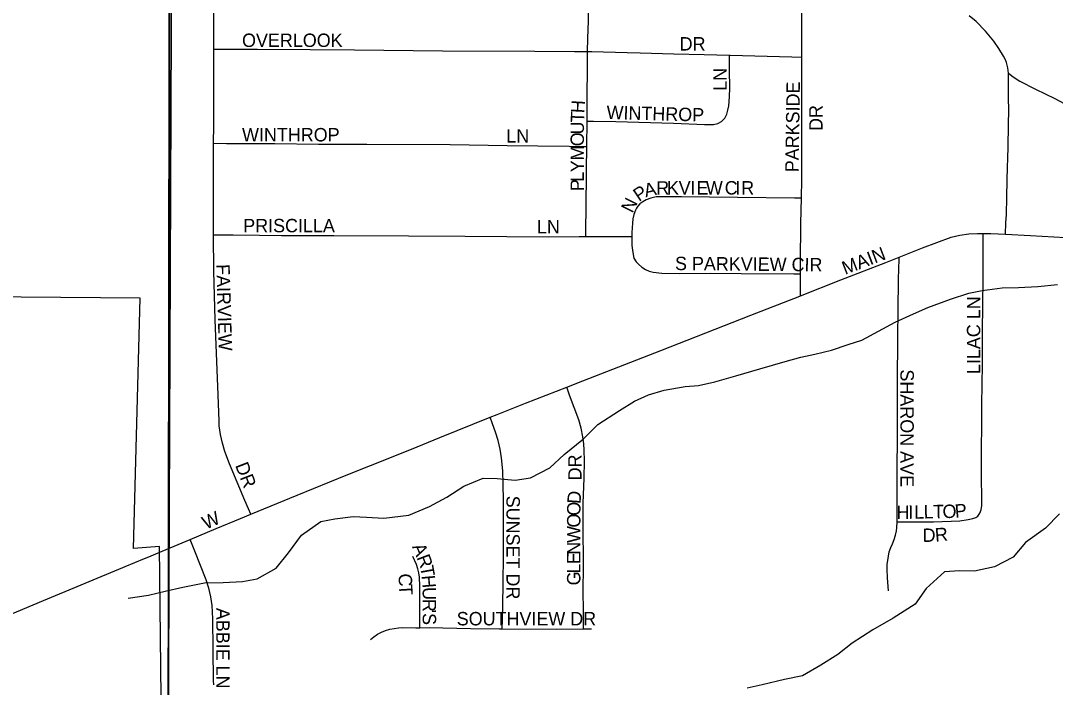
# Model space of a CAD drawing. Extents: x 1874609 to 2204689, y 815661 to 1281160.
# Drawn here: x 2012353 to 2016212, y 1043764 to 1046249 of the extents above; entities that cross this region are included whole.
import ezdxf

# ---------------------------------------------------------------- set-up
doc = ezdxf.new("R2010")
doc.units = 0
for name, color, linetype in [('GM_X_City_Street', 7, 'Continuous'), ('GM_X_City_Street_Text', 7, 'Continuous'), ('GM_X_Corporation', 7, 'Continuous'), ('GM_X_County_Road', 7, 'Continuous'), ('GM_X_Minor_River', 7, 'Continuous'), ('GM_X_Section', 7, 'Continuous'), ('GM_X_Township', 7, 'Continuous')]:
    doc.layers.add(name, color=color, linetype=linetype)

msp = doc.modelspace()

# ---------------------------------------------------------------- linework, layer by layer
at = {"layer": 'GM_X_City_Street'}
for points in [[(2014467, 1046133.5), (2014468, 1046182.8), (2014470.4, 1046248.3), (2014470.7, 1046330.4), (2014471.3, 1046363.2), (2014470.3, 1046444.9), (2014469.9, 1046481.1)], [(2015267, 1046113.2), (2015267.1, 1046181), (2015266.6, 1046262.6), (2015267.1, 1046376.9), (2015267.9, 1046474.8), (2015268, 1046477)], [(2013073.1, 1046143.1), (2013073.4, 1046335.8), (2013076.1, 1046352), (2013080.2, 1046367.8), (2013086.5, 1046383), (2013102.3, 1046411.9)], [(2016037.5, 1046053.3), (2016035.2, 1046072.9), (2016030.4, 1046092.7), (2016026.6, 1046102.2), (2016018.9, 1046117), (2016001.7, 1046145.4), (2015982.5, 1046172.2), (2015951, 1046210.1), (2015916.2, 1046245.4), (2015891, 1046266.9)], [(2013072.5, 1045791.7), (2013073.2, 1045858.2), (2013073.5, 1046022.9), (2013073.1, 1046138.2), (2013073.1, 1046143.1)], [(2013073.1, 1046143.1), (2013101.5, 1046143), (2013154, 1046142.7), (2013236.1, 1046142.5), (2013433.1, 1046141.1), (2013597.4, 1046140.1), (2013925.7, 1046136.9), (2014270.4, 1046135.6), (2014418.1, 1046134), (2014467, 1046133.5)], [(2014465.2, 1045874.2), (2014465.6, 1045920.7), (2014466.6, 1046117.4), (2014467, 1046133.5)], [(2014467, 1046133.5), (2014483.7, 1046133.4), (2014614.8, 1046129.9), (2014663.6, 1046128.3), (2014789.5, 1046125.4), (2014901.9, 1046123), (2014996.7, 1046120.6)], [(2014465.2, 1045874.2), (2014489.9, 1045873.9), (2014572.6, 1045872.6), (2014787.8, 1045867.3), (2014903.5, 1045862), (2014936.6, 1045861.6), (2014952.6, 1045865.7), (2014967.4, 1045873.2), (2014978.8, 1045884.9), (2014986.3, 1045899.7), (2014991, 1045915.6), (2014994, 1045931.9), (2014996.7, 1045964.9), (2014997.4, 1045998), (2014996.5, 1046064.2), (2014996.7, 1046111.4), (2014996.7, 1046120.6)], [(2014996.7, 1046120.6), (2014999.7, 1046120.6), (2015229, 1046114.2), (2015267, 1046113.2)], [(2015264.7, 1045587.1), (2015266, 1045657.1), (2015266, 1045754.4), (2015266, 1045829.5), (2015266.3, 1045859.9), (2015266.7, 1045891.4), (2015267.1, 1046002.4), (2015266.9, 1046034.9), (2015267, 1046113.2)], [(2016025.8, 1045452.7), (2016028, 1045494.9), (2016029.7, 1045526.8), (2016031.4, 1045591), (2016032.4, 1045654.7), (2016033.5, 1045702.2), (2016035, 1045734.6), (2016035.8, 1045778.4), (2016037.3, 1045859.7), (2016038.1, 1045917.3), (2016037.9, 1045958.2), (2016037.6, 1046024.5), (2016037.5, 1046053.3)], [(2016037.5, 1046053.3), (2016055.2, 1046039.1), (2016080, 1046022.9), (2016137.7, 1045993.9), (2016210.1, 1045958.1), (2016295.8, 1045912.2), (2016351.9, 1045879.7), (2016392.3, 1045852.7), (2016437.2, 1045821.3), (2016480.9, 1045788.3), (2016520.8, 1045758.4), (2016556.9, 1045728.4), (2016584.4, 1045704.6), (2016607.8, 1045684.2)], [(2014464.3, 1045779.7), (2014465.2, 1045874.2)], [(2013072.3, 1045450.8), (2013072.2, 1045479.7), (2013072.5, 1045627.9), (2013071.8, 1045726.6), (2013072.5, 1045791.7)], [(2013072.5, 1045791.7), (2013120.2, 1045791.4), (2013132.5, 1045791.4), (2013300.2, 1045790.3), (2013463.8, 1045788.4), (2013643.7, 1045788.2), (2013954.5, 1045786.6), (2014167.1, 1045783.8), (2014281.5, 1045782.7), (2014399.1, 1045780.8), (2014448.3, 1045780), (2014464.3, 1045779.7)], [(2014460.4, 1045444), (2014461.1, 1045477.4), (2014462.6, 1045543.2), (2014463.6, 1045690.9), (2014464.3, 1045779.7)], [(2015264.7, 1045587.1), (2015239.2, 1045587.1), (2015026.4, 1045589.3), (2014817.5, 1045592.6), (2014748.2, 1045592.6), (2014723.5, 1045591.5), (2014702.7, 1045587.1), (2014685.4, 1045580.7), (2014672.9, 1045574.1), (2014662.3, 1045566), (2014655.3, 1045557.8)], [(2015261.7, 1045304.7), (2015261.6, 1045346.7), (2015262.9, 1045493.6), (2015264.7, 1045587.1)], [(2014655.3, 1045557.8), (2014650.1, 1045550.2), (2014645.9, 1045542), (2014640.1, 1045526.5), (2014636.6, 1045510.4), (2014634.4, 1045494), (2014632.1, 1045458.6), (2014632.3, 1045443.7)], [(2013072.3, 1045450.8), (2013101.4, 1045450.8), (2013145.6, 1045450.9), (2013243.6, 1045448.7), (2013325.3, 1045448.5), (2013521.3, 1045448.4), (2013798.9, 1045447.1), (2014011.2, 1045445.2), (2014321.4, 1045443.2), (2014435.8, 1045444.1), (2014460.4, 1045444)], [(2013210.8, 1044409.2), (2013202.2, 1044429.6), (2013189.4, 1044460), (2013132.2, 1044596.7), (2013114.7, 1044642.9), (2013105.3, 1044674.4), (2013098.3, 1044706.5), (2013093.6, 1044739.1), (2013092.5, 1044755.5), (2013089.7, 1044854.1), (2013078.4, 1045133.9), (2013072.7, 1045315), (2013072.3, 1045450.8)], [(2014460.4, 1045444), (2014599, 1045443.8), (2014632.3, 1045443.7)], [(2014632.3, 1045443.7), (2014632.9, 1045411), (2014635.8, 1045384.9), (2014640.2, 1045363.9)], [(2015630, 1045366.8), (2015716.6, 1045401.4), (2015823.8, 1045441.3), (2015839.7, 1045446), (2015856, 1045449.7), (2015888.9, 1045454), (2015922, 1045455.6), (2015943.5, 1045455.5)], [(2015922.7, 1044402.2), (2015930, 1044413.5), (2015935.1, 1044425.4), (2015937.9, 1044441.8), (2015937.9, 1044475.7), (2015937, 1044539.2), (2015936.5, 1044654.8), (2015937.8, 1044736.8), (2015938.1, 1044818.4), (2015940.4, 1044966.6), (2015939.9, 1045032.2), (2015940.7, 1045114.4), (2015941.5, 1045164), (2015942.1, 1045213.2), (2015942.4, 1045262.6), (2015943.5, 1045344.7), (2015943.5, 1045377.8), (2015943.5, 1045410.8), (2015943.5, 1045455.5)], [(2015943.5, 1045455.5), (2015971.4, 1045455.4), (2016025.8, 1045452.7)], [(2016025.8, 1045452.7), (2016118.9, 1045448.1), (2016380.8, 1045433.7), (2016578.2, 1045426.2)], [(2014640.2, 1045363.9), (2014648.8, 1045350.3), (2014657.5, 1045341.1), (2014670, 1045329.8), (2014683, 1045321.4), (2014697.3, 1045315.5), (2014712.5, 1045311.7), (2014744.3, 1045308.1), (2014809.5, 1045306.1), (2014924.8, 1045307), (2015039.7, 1045306.4), (2015236.2, 1045304.9), (2015261.7, 1045304.7)], [(2015261.7, 1045223.4), (2015411.5, 1045282.7), (2015579.8, 1045346.8), (2015630, 1045366.8)], [(2015622.4, 1044381), (2015621.8, 1044430.2), (2015621.8, 1044476.4), (2015622.6, 1044606.4), (2015622.9, 1044665.3), (2015623.4, 1044735.3), (2015622.9, 1044790.8), (2015623.2, 1044848.4), (2015623.6, 1044961.7), (2015624.1, 1045005.5), (2015625.2, 1045073.3), (2015626.3, 1045167.1), (2015627.5, 1045285.8), (2015629.7, 1045359.3), (2015630, 1045366.8)], [(2015261.7, 1045223.4), (2015261.7, 1045265.9), (2015261.7, 1045304.7)], [(2014389.6, 1044882.9), (2014450.1, 1044906.5), (2014740.4, 1045019.5), (2014908.5, 1045084.9), (2015076.1, 1045151.2), (2015259.4, 1045222.4), (2015261.7, 1045223.4)], [(2014103.5, 1044770.4), (2014129.5, 1044780.9), (2014236.2, 1044823), (2014389.6, 1044882.9)], [(2014451.7, 1043981.4), (2014451.6, 1044015.2), (2014451.5, 1044042.5), (2014451.4, 1044129.5), (2014451.7, 1044206.5), (2014451.5, 1044269.4), (2014451.3, 1044318.8), (2014451.1, 1044450.3), (2014454, 1044542.9), (2014455.3, 1044608.6), (2014454.1, 1044647.2), (2014452.8, 1044672), (2014449.5, 1044697.1), (2014443.3, 1044729.6), (2014434.6, 1044761.2), (2014400.5, 1044853.2), (2014389.6, 1044882.9)], [(2013210.8, 1044409.2), (2013384.6, 1044480.4), (2013567, 1044554.2), (2013658.2, 1044590.8), (2013810.4, 1044651.8), (2013916.7, 1044695), (2014103.5, 1044770.4)], [(2014149.3, 1043981.6), (2014149.9, 1044014.6), (2014152.3, 1044141.8), (2014153.6, 1044263.5), (2014153.6, 1044459.7), (2014152.6, 1044521.2), (2014151.4, 1044570.4), (2014146.4, 1044619.3), (2014141, 1044651.7), (2014133.7, 1044683.6), (2014124, 1044715), (2014112.6, 1044745.8), (2014103.5, 1044770.4)], [(2012984.7, 1044314.9), (2013081.4, 1044355.6), (2013172.2, 1044393.4), (2013210.8, 1044409.2)], [(2015622.4, 1044381), (2015639, 1044380.8), (2015676.8, 1044380.2), (2015758.2, 1044381.2), (2015855.5, 1044385), (2015887.5, 1044389.2), (2015904, 1044392.6), (2015915.3, 1044396.6), (2015922.7, 1044402.2)], [(2015589.5, 1044123.4), (2015588.5, 1044139.5), (2015586, 1044172), (2015585, 1044204.8), (2015585.4, 1044221.1), (2015589.5, 1044253.3), (2015592.4, 1044269.3), (2015597.9, 1044284.6), (2015605.1, 1044299.2), (2015610.5, 1044314.5), (2015615.8, 1044330.5), (2015619.2, 1044346.9), (2015620.9, 1044359.9), (2015622.4, 1044381)], [(2012847.6, 1044257.4), (2012880.6, 1044271.1), (2012984.7, 1044314.9)], [(2013072.6, 1043772.6), (2013072.2, 1043789.1), (2013070.7, 1043904.3), (2013069.6, 1044019.6), (2013067.2, 1044068.9), (2013062.6, 1044101.5), (2013055, 1044133.5), (2013044.9, 1044164.8), (2013001.9, 1044271.8), (2012984.7, 1044314.9)], [(2013841.8, 1043986.1), (2013841.7, 1044026.9), (2013841.4, 1044141.5), (2013839.9, 1044174.2), (2013837.7, 1044190.3), (2013834.2, 1044206.1), (2013828.7, 1044221.6), (2013815, 1044251.3)], [(2013658.1, 1043942), (2013670.6, 1043952.5), (2013684.1, 1043961.8), (2013698.5, 1043969.6), (2013713.7, 1043975.7), (2013729.3, 1043980.4), (2013745.3, 1043983.5), (2013761.6, 1043985.3), (2013778, 1043986.2), (2013827.1, 1043986.1), (2013841.8, 1043986.1)], [(2013841.8, 1043986.1), (2013876.1, 1043986.3), (2014030.6, 1043982.9), (2014138.3, 1043981.7), (2014149.3, 1043981.6)], [(2014149.3, 1043981.6), (2014351.2, 1043980.3), (2014451.7, 1043981.4)], [(2014451.7, 1043981.4), (2014482, 1043981.8)]]:
    msp.add_lwpolyline(points, dxfattribs=at)
at = {"layer": 'GM_X_Corporation'}
msp.add_lwpolyline([(2010048.7, 1041405.7), (2010287.2, 1041403.4), (2010287.3, 1041646.5), (2010579.3, 1041646.5), (2010579.4, 1043188.1), (2011124.6, 1043188), (2011247.5, 1042490.5), (2012113.3, 1042894.2), (2012352.9, 1041534.6), (2012140.1, 1041385.6), (2013525.3, 1041372.3), (2013561.3, 1042582.1), (2012889.8, 1042600.8), (2012870.5, 1044289.2), (2012774, 1044281.2), (2012798.1, 1045214.1), (2010579, 1045233.5), (2010579.1, 1046516.9), (2010425.9, 1046511), (2010421.8, 1047312.9), (2010245.1, 1047314.3)], dxfattribs=at)
at = {"layer": 'GM_X_County_Road'}
msp.add_lwpolyline([(2010258.4, 1043876.4), (2010450.6, 1043874.2), (2010598.2, 1043872.7), (2011139.3, 1043861.3), (2011336, 1043855.8), (2011680.2, 1043849.1), (2011745.5, 1043849.5), (2011794.4, 1043852.4), (2011842.8, 1043858.6), (2011890.6, 1043868.5), (2011937.5, 1043881.9), (2011998.8, 1043904.3), (2012119.8, 1043954.3), (2012437.4, 1044088), (2012734.3, 1044211), (2012742.7, 1044214.4), (2012814.2, 1044243.4), (2012830.4, 1044250.1), (2012847.6, 1044257.4)], dxfattribs=at)
at = {"layer": 'GM_X_Minor_River'}
for points in [[(2012753.2, 1044096.1), (2012829.4, 1044107.9), (2012891.6, 1044121.7), (2012957.9, 1044137.5), (2013038.1, 1044153.3), (2013108.3, 1044155), (2013180.6, 1044158.8), (2013234.8, 1044168.7), (2013305.1, 1044208.5), (2013351.4, 1044264.6), (2013399.7, 1044330.6), (2013472, 1044382.5), (2013524.2, 1044392.4), (2013592.4, 1044400.2), (2013642.6, 1044398), (2013706.8, 1044393.8), (2013801.1, 1044405.5), (2013877.4, 1044437.3), (2013941.7, 1044473.2), (2014006, 1044513.1), (2014078.3, 1044542.9), (2014130.4, 1044542.8), (2014196.6, 1044536.5), (2014254.8, 1044544.3), (2014327.1, 1044582.2), (2014379.4, 1044632.2), (2014451.8, 1044690.1), (2014506.1, 1044744.1), (2014586.4, 1044796), (2014642.7, 1044829.9), (2014694.9, 1044853.8), (2014753.1, 1044871.7), (2014831.4, 1044885.4), (2014881.6, 1044889.3), (2014941.8, 1044903.1), (2015020.1, 1044924.9), (2015110.4, 1044950.7), (2015204.8, 1044978.5), (2015263, 1044994.3), (2015315.2, 1045006.2), (2015377.4, 1045020), (2015439.6, 1045041.8), (2015489.8, 1045057.7), (2015614.4, 1045125.5), (2015682.7, 1045155.4), (2015736.9, 1045179.3), (2015821.2, 1045211.1), (2015889.5, 1045232.9), (2015939.6, 1045242.8), (2016013.9, 1045252.5), (2016074.1, 1045254.3), (2016146.3, 1045258.1), (2016220.5, 1045265.9)], [(2016228.1, 1044411), (2016175.8, 1044357), (2016101.4, 1044303.1), (2016055.2, 1044249.1), (2015984.8, 1044213.2), (2015910.6, 1044197.4), (2015854.4, 1044197.6), (2015798.2, 1044193.8), (2015729.9, 1044131.9), (2015689.6, 1044073.8), (2015607.2, 1044021.9), (2015530.9, 1043978), (2015454.5, 1043928.1), (2015400.2, 1043886.2), (2015337.9, 1043846.3), (2015269.6, 1043806.4), (2015201.4, 1043792.6), (2015119.1, 1043772.8), (2015062.9, 1043761)]]:
    msp.add_lwpolyline(points, dxfattribs=at)
at = {"layer": 'GM_X_Section'}
for points in [[(2012915.3, 1046513.3), (2012892.7, 1041156.5), (2007599.8, 1041247.3), (2007626.4, 1046598.1)], [(2019020.7, 1046448.2), (2018988, 1041097.3), (2012892.7, 1041156.5), (2012915.3, 1046513.3)]]:
    msp.add_lwpolyline(points, close=True, dxfattribs=at)
at = {"layer": 'GM_X_Township'}
for points in [[(2012924.9, 1056002.2), (2012935.3, 1053679.3), (2012914.5, 1051827.7), (2012910.2, 1048822.6), (2012903.7, 1044302.1), (2012899.1, 1041173.4), (2012896.1, 1039044.8), (2012861.2, 1035880.2), (2012864.4, 1032937.1), (2012859.2, 1032479.4), (2012845.9, 1030538.4), (2012837.6, 1027645.9), (2012830.6, 1025241.9), (2010175.8, 1025275.6)], [(2037504.4, 1025002.2), (2030477.9, 1025070.5), (2023338.3, 1025139.8), (2019554.9, 1025176.6), (2018880.2, 1025183.1), (2014559, 1025225.1), (2013359, 1025236.7), (2012830.6, 1025241.9), (2012837.6, 1027645.9), (2012845.9, 1030538.4), (2012859.2, 1032479.4), (2012864.4, 1032937.1), (2012861.2, 1035880.2), (2012896.1, 1039044.8), (2012899.1, 1041173.4), (2012903.7, 1044302.1), (2012910.2, 1048822.6), (2012914.5, 1051827.7), (2012935.3, 1053679.3), (2012924.9, 1056002.2)]]:
    msp.add_lwpolyline(points, dxfattribs=at)

# ---------------------------------------------------------------- texts
at = {"layer": 'GM_X_City_Street_Text'}
for s, rotation, p in [('OVERLOOK', 0, (2013178.4, 1046150.7)), ('DR', 0, (2014810.8, 1046137.5)), ('LN', 90, (2014986.2, 1045987.3)), ('PARKSIDE', 89.1565, (2015254.5, 1045683.5)), ('H', 87.0263, (2014455.3, 1045903)), ('WINTHROP', 358.453, (2014537.6, 1045882.3)), ('DR', 90, (2015344, 1045837.7)), ('T', 87.8415, (2014454, 1045868)), ('U', 89.6721, (2014453.8, 1045824.5)), ('WINTHROP', 0, (2013178.4, 1045798.7)), ('LN', 0, (2014164, 1045794.3)), ('O', 89.9928, (2014453.8, 1045780.5)), ('M', 89.9818, (2014453.8, 1045727.7)), ('Y', 89.9781, (2014453.8, 1045683.7)), ('L', 89.9956, (2014453.8, 1045648.5)), ('P', 89.9727, (2014453.7, 1045613.3)), ('P', 33.8795, (2014659, 1045572.4)), ('A', 13.5221, (2014684, 1045590.1)), ('R', 0.9472, (2014723.9, 1045600)), ('K', 0.0437, (2014763.3, 1045600.7)), ('V', 0, (2014807.2, 1045600.7)), ('I', 0, (2014851.2, 1045600.7)), ('E', 0, (2014873.2, 1045600.7)), ('W', 0, (2014908.4, 1045600.7)), ('C', 0, (2014978.8, 1045600.7)), ('I', 0, (2015018.4, 1045600.7)), ('R', 0, (2015040.4, 1045600.7)), ('N', 63.7087, (2014634.7, 1045528.7)), ('PRISCILLA', 0, (2013182.8, 1045459.9)), ('LN', 0, (2014278.4, 1045455.5)), ('MAIN', 20.925, (2015427.8, 1045300.9)), ('S PARKVIEW CIR', 359.4792, (2014793.3, 1045319.1)), ('FAIRVIEW', 271.706, (2013082.2, 1045340.6)), ('LILAC LN', 90, (2015932.1, 1044931.3)), ('SHARON AVE', 270, (2015634.2, 1044948.9)), ('DR', 90, (2014445, 1044535.3)), ('DR', 291.2529, (2013151.9, 1044591.5)), ('SUNSET DR', 270, (2014164.6, 1044478.1)), ('D', 86.0841, (2014441, 1044446.4)), ('O', 89.4754, (2014440.7, 1044403.2)), ('H', 1.2458, (2015620.2, 1044390.7)), ('I', 1.2245, (2015664.2, 1044391.7)), ('L', 1.2378, (2015686.2, 1044392.1)), ('L', 1.2495, (2015721.4, 1044392.9)), ('T', 1.2293, (2015756.6, 1044393.7)), ('O', 1.2438, (2015791.8, 1044394.4)), ('P', 4.694, (2015839.1, 1044395.5)), ('W', 24.5873, (2013043.9, 1044350.9)), ('O', 89.9781, (2014440.6, 1044359.3)), ('W', 89.9798, (2014440.6, 1044302.1)), ('D', 1.071, (2015717.4, 1044305.6)), ('R', 4.9331, (2015765, 1044306.6)), ('A', 292.8771, (2013811.8, 1044288.3)), ('N', 89.9703, (2014440.6, 1044258.1)), ('R', 290.6243, (2013828.7, 1044248.2)), ('E', 89.9707, (2014440.6, 1044222.9)), ('T', 280.2438, (2013842, 1044213.5)), ('L', 89.9727, (2014440.6, 1044187.7)), ('C', 272.1858, (2013761.8, 1044187.2)), ('H', 274.9234, (2013848.1, 1044180.1)), ('G', 89.9781, (2014440.6, 1044143.7)), ('T', 273.292, (2013763.3, 1044146.6)), ('U', 270.4591, (2013851.8, 1044137.2)), ('R', 270, (2013852.2, 1044093.4)), ('ABBIE LN', 270, (2013082, 1044060.1)), ("'", 269.9895, (2013852.2, 1044053.8)), ('SOUTHVIEW DR', 0, (2013979.2, 1043994.7)), ('S', 269.9956, (2013852.2, 1044040.6))]:
    msp.add_text(s, height=50, rotation=rotation, dxfattribs=at).set_placement(p)

doc.saveas('drawing.dxf')
